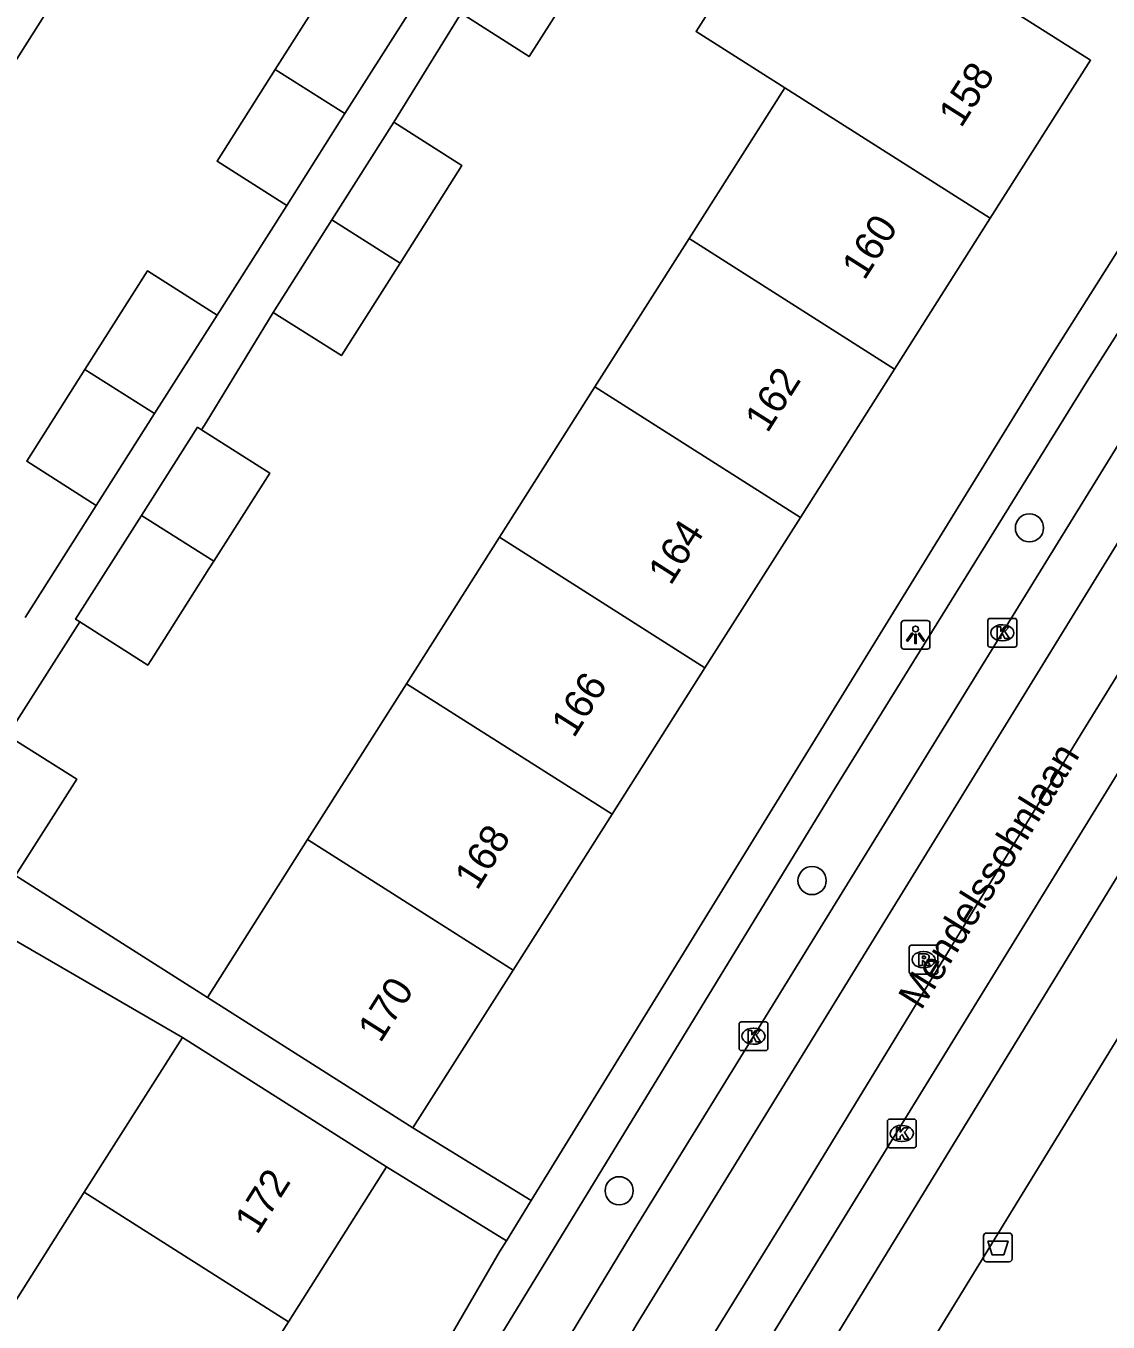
# Model space of a CAD drawing. Extents: x 159040 to 160094, y 381214 to 382518.
# Drawn here: x 159378.8 to 159416.4, y 381801.38 to 381846.41 of the extents above; entities that cross this region are included whole.
import ezdxf

# ---------------------------------------------------------------- set-up
doc = ezdxf.new("R2010")
doc.units = 0
for name, color, linetype in [('IMGEO_Afvalbak', 7, 'Continuous'), ('IMGEO_Boom', 7, 'Continuous'), ('IMGEO_Kolk', 7, 'Continuous'), ('IMGEO_Lichtpunt', 7, 'Continuous'), ('IMGEO_Openbare_ruimte_label', 7, 'Continuous'), ('IMGEO_Pand', 7, 'Continuous'), ('IMGEO_Pand_nummerreeks', 7, 'Continuous'), ('IMGEO_Rijbaan_lokaal_gesloten', 7, 'Continuous'), ('IMGEO_Rioolput', 7, 'Continuous'), ('IMGEO_Voetpad_open', 7, 'Continuous')]:
    doc.layers.add(name, color=color, linetype=linetype)

msp = doc.modelspace()

# ---------------------------------------------------------------- linework, layer by layer
at = {"layer": 'IMGEO_Afvalbak'}
for p, q in [((159412.075, 381803.574), (159412.075, 381804.374)), ((159412.075, 381804.374), (159412.075, 381803.574)), ((159412.175, 381804.474), (159412.965, 381804.474)), ((159412.965, 381804.474), (159412.175, 381804.474)), ((159413.065, 381804.374), (159413.065, 381803.574)), ((159413.065, 381803.574), (159413.065, 381804.374)), ((159412.965, 381803.474), (159412.175, 381803.474)), ((159412.175, 381803.474), (159412.965, 381803.474))]:
    msp.add_line(p, q, dxfattribs=at)
msp.add_lwpolyline([(159412.218, 381804.188), (159412.922, 381804.188), (159412.773, 381803.718), (159412.367, 381803.718), (159412.218, 381804.188)], dxfattribs=at)
for centre, start, end in [((159412.175, 381804.374), 90, 180), ((159412.175, 381804.374), 90, 180), ((159412.965, 381804.374), 0, 90), ((159412.965, 381804.374), 360, 90), ((159412.175, 381803.574), 180, 270), ((159412.175, 381803.574), 180, 270), ((159412.965, 381803.574), 270, 0), ((159412.965, 381803.574), 270, 0)]:
    msp.add_arc(centre, 0.1, start, end, dxfattribs=at)
at = {"layer": 'IMGEO_Boom'}
for centre in [(159413.665, 381828.974), (159406.113, 381816.719), (159399.41, 381805.942)]:
    msp.add_circle(centre, 0.489, dxfattribs=at)
at = {"layer": 'IMGEO_Kolk'}
for p, q in [((159412.223, 381824.904), (159412.223, 381825.756)), ((159412.298, 381825.83), (159413.15, 381825.83)), ((159412.711, 381825.61), (159412.736, 381825.61)), ((159413.224, 381825.756), (159413.224, 381824.904)), ((159413.15, 381824.83), (159412.298, 381824.83)), ((159412.734, 381825.05), (159412.709, 381825.05)), ((159403.576, 381810.885), (159403.576, 381811.737)), ((159403.651, 381811.811), (159404.503, 381811.811)), ((159404.064, 381811.591), (159404.089, 381811.591)), ((159404.577, 381811.737), (159404.577, 381810.885)), ((159404.503, 381810.811), (159403.651, 381810.811)), ((159404.087, 381811.031), (159404.062, 381811.031)), ((159408.806, 381808.434), (159409.658, 381808.434)), ((159408.731, 381807.508), (159408.731, 381808.36)), ((159409.219, 381808.214), (159409.244, 381808.214)), ((159409.732, 381808.36), (159409.732, 381807.508)), ((159409.242, 381807.654), (159409.217, 381807.654)), ((159409.658, 381807.434), (159408.806, 381807.434))]:
    msp.add_line(p, q, dxfattribs=at)
for points in [[(159412.223, 381824.904), (159412.223, 381825.756)], [(159412.298, 381825.83), (159413.15, 381825.83)], [(159412.544, 381825.53), (159412.667, 381825.53), (159412.667, 381825.379), (159412.797, 381825.53), (159412.961, 381825.53), (159412.815, 381825.379), (159412.968, 381825.13), (159412.816, 381825.13), (159412.731, 381825.294), (159412.667, 381825.227), (159412.667, 381825.13), (159412.544, 381825.13), (159412.544, 381825.53)], [(159413.224, 381825.756), (159413.224, 381824.904)], [(159413.15, 381824.83), (159412.298, 381824.83)], [(159403.576, 381810.885), (159403.576, 381811.737)], [(159403.651, 381811.811), (159404.503, 381811.811)], [(159404.577, 381811.737), (159404.577, 381810.885)], [(159403.897, 381811.511), (159404.02, 381811.511), (159404.02, 381811.36), (159404.15, 381811.511), (159404.314, 381811.511), (159404.168, 381811.36), (159404.321, 381811.111), (159404.169, 381811.111), (159404.084, 381811.275), (159404.02, 381811.208), (159404.02, 381811.111), (159403.897, 381811.111), (159403.897, 381811.511)], [(159404.503, 381810.811), (159403.651, 381810.811)], [(159408.806, 381808.434), (159409.658, 381808.434)], [(159408.731, 381807.508), (159408.731, 381808.36)], [(159409.052, 381808.134), (159409.175, 381808.134), (159409.175, 381807.983), (159409.305, 381808.134), (159409.469, 381808.134), (159409.323, 381807.983), (159409.476, 381807.734), (159409.324, 381807.734), (159409.239, 381807.898), (159409.175, 381807.831), (159409.175, 381807.734), (159409.052, 381807.734), (159409.052, 381808.134)], [(159409.732, 381808.36), (159409.732, 381807.508)], [(159409.658, 381807.434), (159408.806, 381807.434)]]:
    msp.add_lwpolyline(points, dxfattribs=at)
for centre, start, end in [((159412.3, 381825.754), 91.552, 178.448), ((159412.3, 381825.754), 91.552, 178.448), ((159413.148, 381825.754), 1.552, 88.448), ((159413.148, 381825.754), 1.552, 88.448), ((159412.3, 381824.906), 181.552, 268.448), ((159412.3, 381824.906), 181.552, 268.448), ((159413.148, 381824.906), 271.552, 358.448), ((159413.148, 381824.906), 271.552, 358.448), ((159403.653, 381811.735), 91.552, 178.448), ((159403.653, 381811.735), 91.552, 178.448), ((159404.501, 381811.735), 1.552, 88.448), ((159404.501, 381811.735), 1.552, 88.448), ((159403.653, 381810.887), 181.552, 268.448), ((159403.653, 381810.887), 181.552, 268.448), ((159404.501, 381810.887), 271.552, 358.448), ((159404.501, 381810.887), 271.552, 358.448), ((159408.808, 381808.358), 91.552, 178.448), ((159408.808, 381808.358), 91.552, 178.448), ((159409.656, 381808.358), 1.552, 88.448), ((159409.656, 381808.358), 1.552, 88.448), ((159408.808, 381807.51), 181.552, 268.448), ((159408.808, 381807.51), 181.552, 268.448), ((159409.656, 381807.51), 271.552, 358.448), ((159409.656, 381807.51), 271.552, 358.448)]:
    msp.add_arc(centre, 0.0765, start, end, dxfattribs=at)
for centre, major_axis, ratio, start_param, end_param in [((159412.71, 381825.33), (-0.387, 0.002), 0.722429, 4.712389, 7.853982), ((159412.735, 381825.33), (-0.39, 0.002), 0.717154, 1.570796, 4.712389), ((159404.063, 381811.311), (-0.387, 0.002), 0.722429, 4.712389, 7.853982), ((159404.088, 381811.311), (-0.39, 0.002), 0.717154, 1.570796, 4.712389), ((159409.218, 381807.934), (-0.387, 0.002), 0.722429, 4.712389, 7.853982), ((159409.243, 381807.934), (-0.39, 0.002), 0.717154, 1.570796, 4.712389)]:
    msp.add_ellipse(centre, major_axis=major_axis, ratio=ratio, start_param=start_param, end_param=end_param, dxfattribs=at)
at = {"layer": 'IMGEO_Lichtpunt'}
for p, q in [((159409.211, 381825.662), (159409.211, 381824.855)), ((159409.211, 381825.662), (159409.211, 381824.855)), ((159410.113, 381825.757), (159409.305, 381825.757)), ((159410.113, 381825.757), (159409.305, 381825.757)), ((159410.207, 381824.855), (159410.207, 381825.662)), ((159410.207, 381824.855), (159410.207, 381825.662)), ((159409.305, 381824.761), (159410.113, 381824.761)), ((159409.305, 381824.761), (159410.113, 381824.761))]:
    msp.add_line(p, q, dxfattribs=at)
for points in [[(159409.585, 381825.326), (159409.624, 381825.298), (159409.436, 381825.036), (159409.398, 381825.063), (159409.585, 381825.326)], [(159409.687, 381825.278), (159409.734, 381825.278), (159409.734, 381824.956), (159409.687, 381824.956), (159409.687, 381825.278)], [(159409.797, 381825.298), (159409.835, 381825.325), (159410.022, 381825.063), (159409.983, 381825.035), (159409.797, 381825.298)]]:
    msp.add_lwpolyline(points, dxfattribs=at)
msp.add_circle((159409.71, 381825.46), 0.0994, dxfattribs=at)
for centre, start, end in [((159409.305, 381825.662), 90, 180), ((159409.305, 381825.662), 90, 180), ((159410.113, 381825.662), 0, 90), ((159410.113, 381825.662), 0, 90), ((159409.305, 381824.855), 180, 270), ((159409.305, 381824.855), 180, 270), ((159410.113, 381824.855), 270, 0), ((159410.113, 381824.855), 270, 360)]:
    msp.add_arc(centre, 0.0946, start, end, dxfattribs=at)
at = {"layer": 'IMGEO_Pand'}
for points in [[(159412.302, 381839.731), (159415.788, 381845.224), (159408.646, 381849.756), (159405.57, 381851.708), (159402.084, 381846.218), (159405.161, 381844.265)], [(159380.886, 381849.076), (159377.596, 381843.891)], [(159398.342, 381848.595), (159396.283, 381845.35), (159393.916, 381846.853)], [(159387.462, 381844.903), (159389.634, 381848.324), (159392.053, 381846.789)], [(159392.053, 381846.789), (159389.882, 381843.368)], [(159387.859, 381840.179), (159385.439, 381841.715), (159387.462, 381844.903)], [(159387.462, 381844.903), (159389.882, 381843.368)], [(159401.837, 381839.027), (159405.161, 381844.265)], [(159405.161, 381844.265), (159412.302, 381839.731)], [(159389.882, 381843.368), (159387.859, 381840.179)], [(159391.581, 381843.065), (159389.429, 381839.673)], [(159391.796, 381838.171), (159393.948, 381841.563), (159391.581, 381843.065)], [(159387.39, 381836.462), (159389.429, 381839.673)], [(159389.429, 381839.673), (159391.796, 381838.171)], [(159412.302, 381839.731), (159408.979, 381834.494)], [(159398.566, 381833.873), (159401.837, 381839.027)], [(159408.979, 381834.494), (159401.837, 381839.027)], [(159391.796, 381838.171), (159389.757, 381834.959), (159387.39, 381836.462)], [(159380.847, 381834.478), (159383.019, 381837.9), (159385.438, 381836.365)], [(159385.438, 381836.365), (159383.267, 381832.943)], [(159381.244, 381829.755), (159378.824, 381831.291), (159380.847, 381834.478)], [(159380.847, 381834.478), (159383.267, 381832.943)], [(159408.979, 381834.494), (159405.707, 381829.34)], [(159395.251, 381828.65), (159398.566, 381833.873)], [(159398.566, 381833.873), (159405.707, 381829.34)], [(159383.267, 381832.943), (159381.244, 381829.755)], [(159384.902, 381832.38), (159384.76, 381832.47), (159382.814, 381829.405)], [(159385.322, 381827.812), (159387.268, 381830.878), (159384.902, 381832.38)], [(159382.814, 381829.405), (159380.525, 381825.797), (159380.666, 381825.707)], [(159385.322, 381827.812), (159382.814, 381829.405)], [(159405.707, 381829.34), (159402.392, 381824.117)], [(159392.021, 381823.561), (159395.251, 381828.65)], [(159395.251, 381828.65), (159402.392, 381824.117)], [(159380.666, 381825.707), (159383.033, 381824.205), (159383.238, 381824.527), (159385.156, 381827.55), (159385.322, 381827.812)], [(159402.392, 381824.117), (159399.163, 381819.028)], [(159392.021, 381823.561), (159388.584, 381818.146)], [(159399.163, 381819.028), (159392.021, 381823.561)], [(159378.44, 381816.892), (159380.564, 381820.24), (159378.163, 381821.763)], [(159395.726, 381813.612), (159399.163, 381819.028)], [(159385.104, 381812.662), (159388.584, 381818.146)], [(159388.584, 381818.146), (159395.726, 381813.612)], [(159395.726, 381813.612), (159392.246, 381808.129)], [(159392.246, 381808.129), (159388.025, 381810.808), (159385.104, 381812.662)], [(159384.239, 381811.27), (159380.824, 381805.889)], [(159391.331, 381806.769), (159387.109, 381809.448), (159384.239, 381811.27)], [(159387.916, 381801.388), (159391.331, 381806.769)], [(159380.824, 381805.889), (159377.508, 381800.663)], [(159380.824, 381805.889), (159387.916, 381801.388)], [(159384.599, 381796.162), (159387.916, 381801.388)]]:
    msp.add_lwpolyline(points, dxfattribs=at)
at = {"layer": 'IMGEO_Rijbaan_lokaal_gesloten'}
for points in [[(159422.676, 381841.238), (159417.421, 381832.946), (159399.834, 381804.431), (159396.798, 381799.408), (159388.803, 381785.24)], [(159390.157, 381784.008), (159400.004, 381801.271), (159418.168, 381830.791), (159424.166, 381840.264)], [(159426.197, 381838.936), (159420.934, 381830.666), (159415.465, 381821.817), (159405.571, 381805.619), (159401.306, 381798.719), (159397.405, 381792.005), (159394.274, 381786.572)], [(159393.013, 381780.216), (159394.802, 381783.778), (159396.213, 381786.294), (159400.746, 381794.258), (159404.64, 381800.812), (159418.936, 381824.033), (159427.699, 381837.953)]]:
    msp.add_lwpolyline(points, dxfattribs=at)
at = {"layer": 'IMGEO_Rioolput'}
for p, q in [((159409.486, 381813.545), (159409.486, 381814.397)), ((159409.561, 381814.471), (159410.413, 381814.471)), ((159410.487, 381814.397), (159410.487, 381813.545)), ((159409.974, 381814.251), (159409.999, 381814.251)), ((159410.413, 381813.471), (159409.561, 381813.471)), ((159409.997, 381813.691), (159409.972, 381813.691))]:
    msp.add_line(p, q, dxfattribs=at)
for points in [[(159409.486, 381813.545), (159409.486, 381814.397)], [(159409.561, 381814.471), (159410.413, 381814.471)], [(159410.487, 381814.397), (159410.487, 381813.545)], [(159410.075, 381814.169), (159409.823, 381814.171), (159409.823, 381813.771)], [(159409.823, 381813.771), (159409.947, 381813.771), (159409.947, 381813.933), (159409.958, 381813.933)], [(159410.001, 381814.09), (159409.947, 381814.09), (159409.947, 381814.009)], [(159409.947, 381814.009), (159409.999, 381814.009)], [(159410.005, 381813.904), (159410.076, 381813.771), (159410.216, 381813.771), (159410.151, 381813.897)], [(159410.413, 381813.471), (159409.561, 381813.471)]]:
    msp.add_lwpolyline(points, dxfattribs=at)
for centre, radius, start, end in [((159409.563, 381814.395), 0.0765, 91.552, 178.448), ((159409.563, 381814.395), 0.0765, 91.552, 178.448), ((159410.411, 381814.395), 0.0765, 1.552, 88.448), ((159410.411, 381814.395), 0.0765, 1.552, 88.448), ((159409.957, 381813.88), 0.0533, 26.0293, 88.6989), ((159409.983, 381814.198), 0.19, 274.7715, 282.9687), ((159410.007, 381813.994), 0.0964, 77.0061, 93.1865), ((159410.021, 381814.051), 0.0378, 276.6634, 79.6772), ((159410.074, 381814.059), 0.109, 350.3612, 89.416), ((159410.072, 381814.059), 0.112, 277.5842, 350.9817), ((159410.056, 381813.844), 0.108, 29.5134, 73.7905), ((159409.563, 381813.547), 0.0765, 181.552, 268.448), ((159409.563, 381813.547), 0.0765, 181.552, 268.448), ((159410.411, 381813.547), 0.0765, 271.552, 358.448), ((159410.411, 381813.547), 0.0765, 271.552, 358.448)]:
    msp.add_arc(centre, radius, start, end, dxfattribs=at)
for centre, major_axis, ratio, start_param, end_param in [((159409.973, 381813.971), (-0.387, 0.002), 0.722429, 4.712389, 7.853982), ((159409.998, 381813.971), (-0.39, 0.002), 0.717154, 1.570796, 4.712389)]:
    msp.add_ellipse(centre, major_axis=major_axis, ratio=ratio, start_param=start_param, end_param=end_param, dxfattribs=at)
at = {"layer": 'IMGEO_Voetpad_open'}
for points in [[(159391.581, 381843.065), (159393.916, 381846.853)], [(159421.364, 381845.906), (159414.422, 381834.943), (159396.349, 381805.602)], [(159386.658, 381785.747), (159394.572, 381799.726), (159406.901, 381819.922), (159415.674, 381834.072), (159420.947, 381842.368), (159422.676, 381841.238)], [(159385.438, 381836.365), (159387.859, 381840.179)], [(159384.902, 381832.38), (159385.062, 381832.633), (159387.39, 381836.462)], [(159428.809, 381836.319), (159420.575, 381823.146), (159407.08, 381801.11), (159405.684, 381798.889), (159402.419, 381793.359), (159396.032, 381782.098)], [(159378.771, 381825.861), (159381.244, 381829.755)], [(159378.163, 381821.763), (159380.666, 381825.707)], [(159397.452, 381778.605), (159397.942, 381779.448), (159402.505, 381787.621), (159406.639, 381794.78), (159421.066, 381818.312)], [(159385.104, 381812.662), (159378.44, 381816.892)], [(159384.239, 381811.27), (159377.22, 381815.334)], [(159396.349, 381805.602), (159392.246, 381808.129)], [(159395.49, 381804.207), (159391.331, 381806.769)], [(159396.349, 381805.602), (159395.49, 381804.207)], [(159395.49, 381804.207), (159395.25, 381803.818), (159385.917, 381787.736), (159385.406, 381786.981)]]:
    msp.add_lwpolyline(points, dxfattribs=at)

# ---------------------------------------------------------------- texts
at = {"layer": 'IMGEO_Openbare_ruimte_label'}
msp.add_text('Mendelssohnlaan', height=1, rotation=58.1222, dxfattribs=at).set_placement((159409.903, 381812.183))
at = {"layer": 'IMGEO_Pand_nummerreeks'}
for s, rotation, p in [('158', 57.5994, (159411.292, 381842.84)), ('160', 57.5991, (159407.929, 381837.542)), ('162', 57.5991, (159404.562, 381832.238)), ('164', 57.5991, (159401.199, 381826.94)), ('166', 57.5991, (159397.836, 381821.641)), ('168', 57.5991, (159394.476, 381816.345)), ('170', 57.5991, (159391.113, 381811.046)), ('172', 57.5978, (159386.833, 381804.385))]:
    msp.add_text(s, height=1, rotation=rotation, dxfattribs=at).set_placement(p)

doc.saveas('drawing.dxf')
